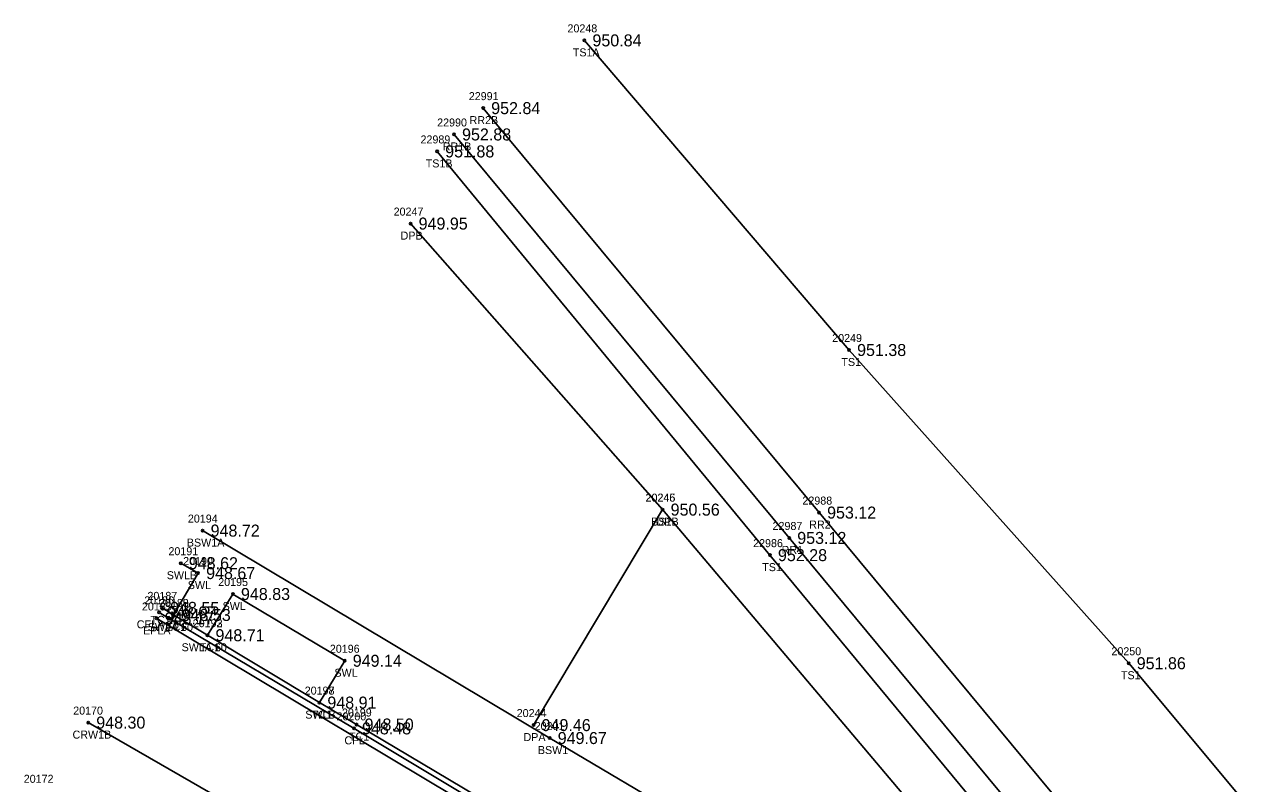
# Model space of a CAD drawing. Extents: x 1576181 to 1577685, y 1099396 to 1101490.
# Drawn here: x 1576201.2 to 1576353, y 1099743.2 to 1099838.1 of the extents above; entities that cross this region are included whole.
import ezdxf

# ---------------------------------------------------------------- set-up
doc = ezdxf.new("R2010")
doc.units = 0
for name, color, linetype in [('RD_DTM_BkLn1', 7, 'Continuous'), ('RD_DTM_BkLn2', 7, 'Continuous'), ('RD_DTM_BkLn_txCode', 7, 'Continuous'), ('RD_EX_Conc', 7, 'Continuous'), ('RD_EX_Conc_txCode', 7, 'Continuous'), ('RD_EX_Driveway', 7, 'Continuous'), ('RD_EX_Driveway_txCode', 7, 'Continuous'), ('RD_EX_RailRoad', 7, 'Continuous'), ('RD_EX_RailRoad_txCode', 7, 'Continuous'), ('RD_EX_Road', 7, 'Continuous'), ('RD_EX_Road_txCode', 7, 'Continuous'), ('RD_EX_TX_Conc_ELEV', 7, 'Continuous'), ('RD_EX_TX_Driveway_ELEV', 7, 'Continuous'), ('RD_EX_TX_Misc_ELEV', 7, 'Continuous'), ('RD_EX_TX_RailRoad_ELEV', 7, 'Continuous'), ('RD_EX_TX_Road_ELEV', 7, 'Continuous'), ('RD_HC_Survey_ELEV', 7, 'Continuous'), ('RD_HC_Survey_txCode', 7, 'Continuous'), ('RD_SMD_Locator', 7, 'Continuous')]:
    doc.layers.add(name, color=color, linetype=linetype)

msp = doc.modelspace()

# ---------------------------------------------------------------- linework, layer by layer
at = {"layer": 'RD_DTM_BkLn1'}
msp.add_lwpolyline([(1576411.06, 1099606.41), (1576377.33, 1099642.66), (1576337.77, 1099673.47), (1576295.75, 1099700.12), (1576252.73, 1099725.71), (1576209.23, 1099750.79)], dxfattribs=at)
at = {"layer": 'RD_DTM_BkLn2'}
for points in [[(1576271.23, 1099836.06), (1576304.3, 1099797.36), (1576339.24, 1099758.21), (1576368.71, 1099722.87), (1576388.13, 1099699.72), (1576412.66, 1099672.77), (1576428.35, 1099666.09)], [(1576397.55, 1099648.8), (1576363.44, 1099688.93), (1576329.97, 1099728.73), (1576294.41, 1099771.72), (1576252.83, 1099822.18)], [(1576386.37, 1099656.97), (1576355.23, 1099693.54), (1576320.63, 1099730.47), (1576281, 1099777.41)], [(1576218.46, 1099765.13), (1576219.9, 1099764.24), (1576224.13, 1099761.71), (1576238.11, 1099753.29), (1576242.76, 1099750.55), (1576264.25, 1099737.75), (1576268.9, 1099734.96), (1576284.22, 1099725.87), (1576285.67, 1099729.37)]]:
    msp.add_lwpolyline(points, dxfattribs=at)
at = {"layer": 'RD_EX_Conc'}
for points in [[(1576223.52, 1099774.79), (1576266.89, 1099748.86), (1576285.18, 1099738.02), (1576289.38, 1099734.13), (1576290.45, 1099731.15), (1576290.26, 1099727.95)], [(1576219.9, 1099764.24), (1576222.96, 1099769.48), (1576220.8, 1099770.71)], [(1576224.13, 1099761.71), (1576227.31, 1099766.86), (1576241.28, 1099758.52), (1576238.11, 1099753.29)], [(1576218.09, 1099764.57), (1576242.44, 1099750.07), (1576263.9, 1099737.2), (1576284.46, 1099725.02), (1576286.16, 1099729.27)]]:
    msp.add_lwpolyline(points, dxfattribs=at)
at = {"layer": 'RD_EX_Driveway'}
msp.add_lwpolyline([(1576264.88, 1099750.48), (1576281, 1099777.41), (1576249.51, 1099813.16)], dxfattribs=at)
at = {"layer": 'RD_EX_RailRoad'}
for points in [[(1576588.64, 1099429.74), (1576556.82, 1099468.27), (1576525.53, 1099505.93), (1576492.19, 1099546.33), (1576461.17, 1099583.65), (1576447.93, 1099599.71), (1576411.91, 1099642.96), (1576369.31, 1099694.21), (1576336.53, 1099733.7), (1576300.55, 1099777.04), (1576258.58, 1099827.59)], [(1576584.91, 1099426.47), (1576552.99, 1099465.14), (1576521.86, 1099502.63), (1576488.35, 1099543.2), (1576457.44, 1099580.52), (1576443.75, 1099596.96), (1576408.06, 1099639.92), (1576365.56, 1099691.12), (1576332.82, 1099730.47), (1576296.82, 1099773.87), (1576254.94, 1099824.3)]]:
    msp.add_lwpolyline(points, dxfattribs=at)
at = {"layer": 'RD_EX_Road'}
msp.add_lwpolyline([(1576217.78, 1099763.81), (1576263.48, 1099736.46), (1576283.45, 1099724.57), (1576282.38, 1099722.88), (1576302.5, 1099710.8), (1576345.46, 1099684.21), (1576368.62, 1099668.36), (1576383.76, 1099654.94), (1576386.09, 1099656.79), (1576408.06, 1099639.92), (1576408.06, 1099639.92), (1576411.91, 1099642.96), (1576420.57, 1099654.58), (1576428.78, 1099665.98), (1576435.66, 1099661.47), (1576436.12, 1099661.14), (1576438.46, 1099659.42), (1576459.37, 1099692.41), (1576486.6, 1099735.59), (1576512.85, 1099776.73), (1576539.46, 1099818.98), (1576543.78, 1099825.47), (1576541.42, 1099827.15), (1576542.92, 1099831.85)], dxfattribs=at)
at = {"layer": 'RD_SMD_Locator'}
for centre in [(1576271.23, 1099836.06), (1576258.58, 1099827.59), (1576254.94, 1099824.3), (1576252.83, 1099822.18), (1576249.51, 1099813.16), (1576304.3, 1099797.36), (1576281, 1099777.41), (1576281, 1099777.41), (1576300.55, 1099777.04), (1576223.52, 1099774.79), (1576296.82, 1099773.87), (1576220.8, 1099770.71), (1576294.41, 1099771.72), (1576222.96, 1099769.48), (1576227.31, 1099766.86), (1576218.09, 1099764.57), (1576218.46, 1099765.13), (1576217.78, 1099763.81), (1576219.9, 1099764.24), (1576219.9, 1099764.24), (1576224.13, 1099761.71), (1576224.13, 1099761.71), (1576241.28, 1099758.52), (1576339.24, 1099758.21), (1576238.11, 1099753.29), (1576238.11, 1099753.29), (1576209.23, 1099750.79), (1576242.44, 1099750.07), (1576242.76, 1099750.55), (1576264.88, 1099750.48), (1576266.89, 1099748.86)]:
    msp.add_circle(centre, 0.15, dxfattribs=at)

# ---------------------------------------------------------------- texts
at = {"layer": 'RD_DTM_BkLn_txCode'}
for s, p in [('20248', (1576269.11, 1099837.06)), ('TS1A', (1576269.78, 1099834.06)), ('22989', (1576250.75, 1099823.18)), ('TS1B', (1576251.4, 1099820.18)), ('20249', (1576302.19, 1099798.36)), ('TS1', (1576303.34, 1099795.36)), ('20246', (1576278.86, 1099778.41)), ('BS1B', (1576279.58, 1099775.41)), ('22986', (1576292.31, 1099772.72)), ('TS1', (1576293.45, 1099769.72)), ('20250', (1576337.08, 1099759.21)), ('TS1', (1576338.27, 1099756.21))]:
    msp.add_text(s, height=1, dxfattribs=at).set_placement(p)
at = {"layer": 'RD_EX_Conc_txCode'}
for s, p in [('20194', (1576221.68, 1099775.79)), ('BSW1A', (1576221.55, 1099772.79)), ('20191', (1576219.25, 1099771.71)), ('20190', (1576221.09, 1099770.48)), ('SWLB', (1576219.04, 1099768.71)), ('SWL', (1576221.67, 1099767.48)), ('20195', (1576225.47, 1099767.86)), ('20186', (1576216.23, 1099765.57)), ('20187', (1576216.63, 1099766.13)), ('20188', (1576218.07, 1099765.24)), ('20189', (1576218.07, 1099765.24)), ('SWL', (1576226.02, 1099764.86)), ('CFLA 18', (1576215.29, 1099762.57)), ('SWLA 60', (1576216.67, 1099762.24)), ('TC1A', (1576217.01, 1099763.13)), ('TC1', (1576218.94, 1099762.24)), ('20192', (1576222.29, 1099762.71)), ('20193', (1576222.29, 1099762.71)), ('SWLA 60', (1576220.9, 1099759.71)), ('TC1', (1576223.17, 1099759.71)), ('20196', (1576239.42, 1099759.52)), ('SWL', (1576239.99, 1099756.52)), ('20197', (1576236.28, 1099754.29)), ('20198', (1576236.28, 1099754.29)), ('20199', (1576240.93, 1099751.55)), ('SWLB', (1576236.35, 1099751.29)), ('TC1', (1576237.15, 1099751.29)), ('20200', (1576240.25, 1099751.07)), ('TC1', (1576241.8, 1099748.55)), ('20201', (1576265.01, 1099749.86)), ('CFL', (1576241.24, 1099748.07)), ('BSW1', (1576265.41, 1099746.86))]:
    msp.add_text(s, height=1, dxfattribs=at).set_placement(p)
at = {"layer": 'RD_EX_Driveway_txCode'}
for s, p in [('20247', (1576247.39, 1099814.16)), ('DPB', (1576248.26, 1099811.16)), ('20245', (1576278.88, 1099778.41)), ('DP', (1576280.22, 1099775.41)), ('20244', (1576262.77, 1099751.48)), ('DPA', (1576263.62, 1099748.48))]:
    msp.add_text(s, height=1, dxfattribs=at).set_placement(p)
at = {"layer": 'RD_EX_RailRoad_txCode'}
for s, p in [('22991', (1576256.78, 1099828.59)), ('22990', (1576252.83, 1099825.3)), ('RR2B', (1576256.88, 1099825.59)), ('RR1B', (1576253.53, 1099822.3)), ('22988', (1576298.47, 1099778.04)), ('22987', (1576294.74, 1099774.87)), ('RR2', (1576299.32, 1099775.04)), ('RR1', (1576295.87, 1099771.87))]:
    msp.add_text(s, height=1, dxfattribs=at).set_placement(p)
at = {"layer": 'RD_EX_Road_txCode'}
for s, p in [('20185', (1576215.94, 1099764.81)), ('EPLA', (1576216.08, 1099761.81)), ('20172', (1576201.17, 1099743.27))]:
    msp.add_text(s, height=1, dxfattribs=at).set_placement(p)
at = {"layer": 'RD_EX_TX_Conc_ELEV'}
for s, p in [('948.72', (1576224.52, 1099774.04)), ('948.62', (1576221.8, 1099769.96)), ('948.67', (1576223.96, 1099768.73)), ('948.83', (1576228.31, 1099766.11)), ('948.07', (1576219.09, 1099763.82)), ('948.55', (1576219.46, 1099764.38)), ('948.53', (1576220.9, 1099763.49)), ('948.53', (1576220.9, 1099763.49)), ('948.71', (1576225.13, 1099760.96)), ('948.71', (1576225.13, 1099760.96)), ('949.14', (1576242.28, 1099757.77)), ('948.91', (1576239.11, 1099752.54)), ('948.91', (1576239.11, 1099752.54)), ('948.50', (1576243.76, 1099749.8)), ('948.48', (1576243.44, 1099749.32)), ('949.67', (1576267.89, 1099748.11))]:
    msp.add_text(s, height=1.5, dxfattribs=at).set_placement(p)
at = {"layer": 'RD_EX_TX_Driveway_ELEV'}
for s, p in [('949.95', (1576250.51, 1099812.41)), ('950.56', (1576282, 1099776.66)), ('949.46', (1576265.88, 1099749.73))]:
    msp.add_text(s, height=1.5, dxfattribs=at).set_placement(p)
at = {"layer": 'RD_EX_TX_Misc_ELEV'}
for s, p in [('950.84', (1576272.23, 1099835.31)), ('951.88', (1576253.83, 1099821.43)), ('951.38', (1576305.3, 1099796.61)), ('950.56', (1576282, 1099776.66)), ('952.28', (1576295.41, 1099770.97)), ('951.86', (1576340.24, 1099757.46))]:
    msp.add_text(s, height=1.5, dxfattribs=at).set_placement(p)
at = {"layer": 'RD_EX_TX_RailRoad_ELEV'}
for s, p in [('952.84', (1576259.58, 1099826.84)), ('952.88', (1576255.94, 1099823.55)), ('953.12', (1576301.55, 1099776.29)), ('953.12', (1576297.82, 1099773.12))]:
    msp.add_text(s, height=1.5, dxfattribs=at).set_placement(p)
at = {"layer": 'RD_EX_TX_Road_ELEV'}
msp.add_text('948.17', height=1.5, dxfattribs=at).set_placement((1576218.78, 1099763.06))
at = {"layer": 'RD_HC_Survey_ELEV'}
msp.add_text('948.30', height=1.5, dxfattribs=at).set_placement((1576210.23, 1099750.04))
at = {"layer": 'RD_HC_Survey_txCode'}
for s, p in [('20170', (1576207.35, 1099751.79)), ('CRW1B', (1576207.27, 1099748.79))]:
    msp.add_text(s, height=1, dxfattribs=at).set_placement(p)

doc.saveas('drawing.dxf')
